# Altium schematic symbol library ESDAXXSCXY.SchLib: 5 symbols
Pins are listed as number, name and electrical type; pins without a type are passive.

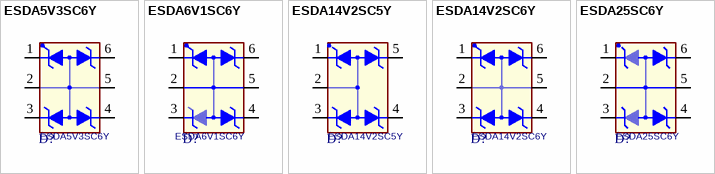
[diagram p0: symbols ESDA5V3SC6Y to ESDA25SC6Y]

## ESDA5V3SC6Y
designator D?
footprint ST_SOT23-6L
pins: 1, 2, 3, 4, 5, 6

## ESDA6V1SC6Y
designator D?
footprint ST_SOT23-6L
pins: 1, 2, 3, 4, 5, 6

## ESDA14V2SC5Y
designator D?
footprint ST_SOT23-5L
pins: 1, 2, 3, 4, 5

## ESDA14V2SC6Y
designator D?
footprint ST_SOT23-6L
pins: 1, 2, 3, 4, 5, 6

## ESDA25SC6Y
designator D?
footprint ST_SOT23-6L
pins: 1, 2, 3, 4, 5, 6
